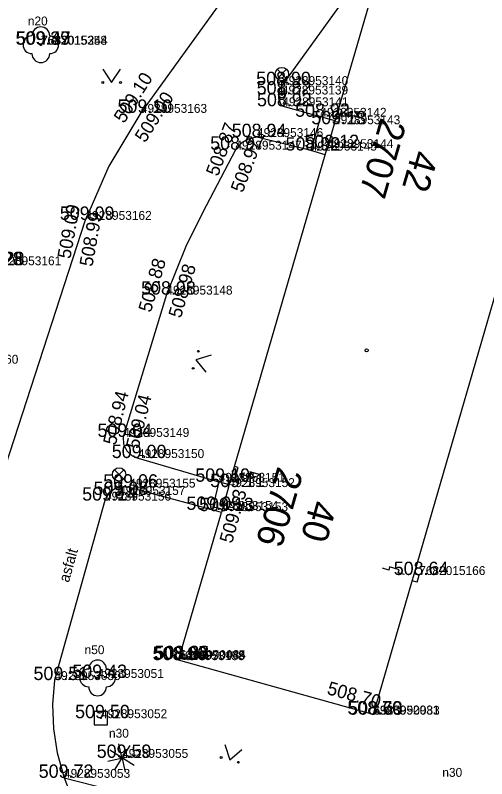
# Model space of a CAD drawing. Extents: x -669251 to -668549, y -1128351 to -1127698.
# Drawn here: x -668787.5 to -668761.03, y -1128134.75 to -1128091.87 of the extents above; entities that cross this region are included whole.
import ezdxf

# ---------------------------------------------------------------- set-up
doc = ezdxf.new("R2010")
doc.units = 0
for name, color, linetype in [('Vrstva 1', 7, 'Continuous'), ('Vrstva 10', 7, 'Continuous'), ('Vrstva 2', 7, 'Continuous'), ('Vrstva 22', 7, 'Continuous'), ('Vrstva 24', 7, 'Continuous'), ('Vrstva 26', 7, 'Continuous'), ('Vrstva 3', 7, 'Continuous'), ('Vrstva 33', 7, 'Continuous'), ('Vrstva 36', 7, 'Continuous'), ('Vrstva 40', 7, 'Continuous'), ('Vrstva 43', 7, 'Continuous'), ('Vrstva 44', 7, 'Continuous'), ('Vrstva 47', 7, 'Continuous'), ('Vrstva 5', 7, 'Continuous'), ('Vrstva 58', 7, 'Continuous'), ('Vrstva 6', 7, 'Continuous')]:
    doc.layers.add(name, color=color, linetype=linetype)

msp = doc.modelspace()

# ---------------------------------------------------------------- linework, layer by layer
at = {"layer": 'Vrstva 1'}
for p, q in [((-668786.069, -1128093.526), (-668786.069, -1128093.526)), ((-668786.04, -1128093.52), (-668786.04, -1128093.52)), ((-668772.52, -1128095.79), (-668772.52, -1128095.79)), ((-668772.53, -1128096.32), (-668772.53, -1128096.32)), ((-668772.51, -1128096.98), (-668772.51, -1128096.98)), ((-668780.45, -1128097.35), (-668780.45, -1128097.35)), ((-668770.37, -1128097.57), (-668770.37, -1128097.57)), ((-668769.6, -1128097.99), (-668769.6, -1128097.99)), ((-668773.93, -1128098.71), (-668773.93, -1128098.71)), ((-668775.14, -1128099.42), (-668775.14, -1128099.42)), ((-668770.91, -1128099.47), (-668770.91, -1128099.47)), ((-668769.99, -1128099.33), (-668769.99, -1128099.33)), ((-668783.56, -1128103.36), (-668783.56, -1128103.36)), ((-668779.02, -1128107.56), (-668779.02, -1128107.56)), ((-668781.45, -1128115.55), (-668781.45, -1128115.55)), ((-668780.61, -1128116.74), (-668780.61, -1128116.74)), ((-668776.08, -1128118.07), (-668776.08, -1128118.07)), ((-668781.1, -1128118.4), (-668781.1, -1128118.4)), ((-668775.52, -1128118.37), (-668775.52, -1128118.37)), ((-668782.47, -1128119.13), (-668782.47, -1128119.13)), ((-668781.67, -1128118.81), (-668781.67, -1128118.81)), ((-668776.45, -1128119.65), (-668776.45, -1128119.65)), ((-668775.9, -1128119.72), (-668775.9, -1128119.72)), ((-668764.82, -1128123.31), (-668764.82, -1128123.31)), ((-668778.34, -1128128.09), (-668778.34, -1128128.09)), ((-668778.295, -1128128.046), (-668778.295, -1128128.046)), ((-668778.271, -1128128.031), (-668778.271, -1128128.031)), ((-668785.3, -1128129.21), (-668785.3, -1128129.21)), ((-668782.88, -1128129.09), (-668782.88, -1128129.09)), ((-668767.4, -1128131.14), (-668767.4, -1128131.14)), ((-668767.385, -1128131.155), (-668767.385, -1128131.155)), ((-668782.69, -1128131.35), (-668782.69, -1128131.35)), ((-668781.51, -1128133.58), (-668781.51, -1128133.58)), ((-668784.77, -1128134.7), (-668784.77, -1128134.7))]:
    msp.add_line(p, q, dxfattribs=at)
at = {"layer": 'Vrstva 10'}
for p, q in [((-668768.553, -1128080.83), (-668780.45, -1128097.35)), ((-668767.52, -1128088.88), (-668772.52, -1128095.79)), ((-668770.37, -1128097.57), (-668772.51, -1128096.98)), ((-668770.37, -1128097.57), (-668770.91, -1128099.47)), ((-668769.545, -1128097.803), (-668770.37, -1128097.57)), ((-668770.91, -1128099.47), (-668773.93, -1128098.71)), ((-668770.097, -1128099.7), (-668770.91, -1128099.47)), ((-668789.953, -1128123.016), (-668783.56, -1128103.36)), ((-668779.02, -1128107.56), (-668781.45, -1128115.55)), ((-668780.61, -1128116.74), (-668776.08, -1128118.07)), ((-668776.08, -1128118.07), (-668776.45, -1128119.65)), ((-668775.483, -1128118.243), (-668776.08, -1128118.07)), ((-668776.45, -1128119.65), (-668781.1, -1128118.4)), ((-668782.47, -1128119.13), (-668785.3, -1128129.21)), ((-668775.924, -1128119.803), (-668776.45, -1128119.65)), ((-668784.765, -1128134.701), (-668756.23, -1128141.93))]:
    msp.add_line(p, q, dxfattribs=at)
for points in [[(-668772.52, -1128095.79), (-668772.695, -1128096.134), (-668772.717, -1128096.519), (-668772.582, -1128096.881), (-668772.51, -1128096.98)], [(-668780.45, -1128097.35), (-668782.25, -1128100.34), (-668783.56, -1128103.36)], [(-668773.93, -1128098.71), (-668774.416, -1128098.822), (-668774.842, -1128099.08), (-668775.14, -1128099.42)], [(-668775.14, -1128099.42), (-668776.987, -1128102.963), (-668777.918, -1128104.855), (-668779.02, -1128107.56)], [(-668781.45, -1128115.55), (-668781.425, -1128115.961), (-668781.247, -1128116.333), (-668780.942, -1128116.609), (-668780.61, -1128116.74)], [(-668781.1, -1128118.4), (-668781.512, -1128118.352), (-668781.911, -1128118.461), (-668782.24, -1128118.713), (-668782.47, -1128119.13)], [(-668785.3, -1128129.21), (-668785.412, -1128130.577), (-668785.365, -1128131.947), (-668785.158, -1128133.303), (-668784.765, -1128134.701)], [(-668784.765, -1128134.701), (-668784.281, -1128135.897), (-668783.622, -1128137.1), (-668783.36, -1128137.5)]]:
    msp.add_lwpolyline(points, dxfattribs=at)
at = {"layer": 'Vrstva 22'}
for p, q in [((-668781.518, -1128133.54), (-668781.69, -1128132.786)), ((-668781.076, -1128132.89), (-668781.49, -1128133.546)), ((-668781.544, -1128133.56), (-668782.2, -1128133.146)), ((-668782.304, -1128133.76), (-668781.55, -1128133.588)), ((-668781.53, -1128133.614), (-668781.944, -1128134.27)), ((-668781.502, -1128133.62), (-668781.33, -1128134.374)), ((-668780.82, -1128134.014), (-668781.476, -1128133.6)), ((-668781.47, -1128133.572), (-668780.716, -1128133.4))]:
    msp.add_line(p, q, dxfattribs=at)
for centre, radius in [((-668786.069, -1128093.526), 0.05), ((-668782.88, -1128129.09), 0.05), ((-668781.51, -1128133.58), 0.04)]:
    msp.add_circle(centre, radius, dxfattribs=at)
for centre, start, end in [((-668786.069, -1128093.026), 0, 180), ((-668786.569, -1128093.526), 90, 270), ((-668785.569, -1128093.526), 270, 90), ((-668786.069, -1128094.026), 180, 0), ((-668782.88, -1128128.59), 0, 180), ((-668783.38, -1128129.09), 90, 270), ((-668782.38, -1128129.09), 270, 90), ((-668782.88, -1128129.59), 180, 0)]:
    msp.add_arc(centre, 0.5, start, end, dxfattribs=at)
at = {"layer": 'Vrstva 24'}
for p, q in [((-668769.155, -1128097.182), (-668769.347, -1128097.126)), ((-668769.239, -1128097.47), (-668769.155, -1128097.182)), ((-668767.854, -1128097.458), (-668768.455, -1128097.282)), ((-668768.455, -1128097.282), (-668768.165, -1128097.627)), ((-668769.431, -1128097.414), (-668769.239, -1128097.47)), ((-668768.739, -1128097.345), (-668769.005, -1128097.382)), ((-668768.165, -1128097.627), (-668769.005, -1128097.382)), ((-668769.005, -1128097.382), (-668768.801, -1128097.556)), ((-668774.993, -1128117.273), (-668775.185, -1128117.217)), ((-668775.16, -1128117.849), (-668774.993, -1128117.273)), ((-668775.352, -1128117.793), (-668775.16, -1128117.849)), ((-668774.618, -1128117.58), (-668774.884, -1128117.617)), ((-668774.044, -1128117.861), (-668774.884, -1128117.617)), ((-668774.884, -1128117.617), (-668774.679, -1128117.791)), ((-668773.733, -1128117.691), (-668774.334, -1128117.516)), ((-668774.334, -1128117.516), (-668774.044, -1128117.861)), ((-668765.107, -1128123.228), (-668764.82, -1128123.311)), ((-668764.937, -1128123.713), (-668764.82, -1128123.311)), ((-668764.937, -1128123.713), (-668765.223, -1128123.63))]:
    msp.add_line(p, q, dxfattribs=at)
msp.add_lwpolyline([(-668765.647, -1128123.289), (-668766, -1128123.185), (-668765.949, -1128123.01), (-668766.479, -1128122.856), (-668766.531, -1128123.031), (-668766.885, -1128122.93)], dxfattribs=at)
at = {"layer": 'Vrstva 26'}
msp.add_lwpolyline([(-668783.065, -1128131.725), (-668782.315, -1128131.725), (-668782.315, -1128130.975), (-668783.065, -1128130.975)], close=True, dxfattribs=at)
msp.add_circle((-668782.69, -1128131.35), 0.02, dxfattribs=at)
at = {"layer": 'Vrstva 33'}
for p, q in [((-668772.795, -1128094.905), (-668772.265, -1128095.435)), ((-668772.795, -1128095.435), (-668772.265, -1128094.905)), ((-668772.53, -1128096.32), (-668772.53, -1128095.545)), ((-668781.935, -1128117.395), (-668781.405, -1128117.925)), ((-668781.935, -1128117.925), (-668781.405, -1128117.395)), ((-668781.67, -1128118.81), (-668781.67, -1128118.035))]:
    msp.add_line(p, q, dxfattribs=at)
for centre, radius in [((-668772.53, -1128095.17), 0.375), ((-668772.53, -1128096.32), 0.19), ((-668772.53, -1128096.32), 0.05), ((-668781.67, -1128117.66), 0.375), ((-668781.67, -1128118.81), 0.19), ((-668781.67, -1128118.81), 0.05)]:
    msp.add_circle(centre, radius, dxfattribs=at)
at = {"layer": 'Vrstva 36'}
for p, q in [((-668782.591, -1128094.897), (-668782.091, -1128095.647)), ((-668782.091, -1128095.647), (-668781.591, -1128094.897)), ((-668776.506, -1128110.961), (-668777.369, -1128111.221)), ((-668777.369, -1128111.221), (-668776.797, -1128111.918)), ((-668775.738, -1128132.836), (-668775.458, -1128133.693)), ((-668775.458, -1128133.693), (-668774.775, -1128133.105))]:
    msp.add_line(p, q, dxfattribs=at)
for centre in [(-668782.591, -1128095.647), (-668781.591, -1128095.647), (-668777.224, -1128110.743), (-668777.514, -1128111.699), (-668775.94, -1128133.559), (-668774.976, -1128133.827)]:
    msp.add_circle(centre, 0.05, dxfattribs=at)
at = {"layer": 'Vrstva 5'}
for p, q in [((-668769.545, -1128097.803), (-668767.17, -1128089.67)), ((-668756.25, -1128092.67), (-668767.4, -1128131.14)), ((-668769.6, -1128097.99), (-668769.545, -1128097.803)), ((-668770.097, -1128099.7), (-668769.99, -1128099.33)), ((-668775.483, -1128118.243), (-668770.097, -1128099.7)), ((-668775.52, -1128118.37), (-668775.483, -1128118.243)), ((-668778.34, -1128128.09), (-668775.924, -1128119.803)), ((-668767.4, -1128131.14), (-668778.34, -1128128.09))]:
    msp.add_line(p, q, dxfattribs=at)
at = {"layer": 'Vrstva 58'}
msp.add_circle((-668767.773, -1128110.693), 0.0875, dxfattribs=at)
at = {"layer": 'Vrstva 6'}
for p, q in [((-668769.6, -1128097.99), (-668769.99, -1128099.33)), ((-668775.52, -1128118.37), (-668775.924, -1128119.803))]:
    msp.add_line(p, q, dxfattribs=at)

# ---------------------------------------------------------------- texts
at = {"layer": 'Vrstva 2'}
for s, p in [('7682015358', (-668786.069, -1128093.526)), ('7682015244', (-668786.04, -1128093.52)), ('4928953140', (-668772.52, -1128095.79)), ('4928953139', (-668772.53, -1128096.32)), ('4928953141', (-668772.51, -1128096.98)), ('4928953163', (-668780.45, -1128097.35)), ('4928953142', (-668770.37, -1128097.57)), ('4928953143', (-668769.6, -1128097.99)), ('4928953146', (-668773.93, -1128098.71)), ('4928953147', (-668775.14, -1128099.42)), ('4928953145', (-668770.91, -1128099.47)), ('4928953144', (-668769.99, -1128099.33)), ('4928953162', (-668783.56, -1128103.36)), ('4928953161', (-668788.64, -1128105.91)), ('4928953148', (-668779.02, -1128107.56)), ('4928953160', (-668791.05, -1128111.44)), ('4928953149', (-668781.45, -1128115.55)), ('4928953150', (-668780.61, -1128116.74)), ('4928953155', (-668781.1, -1128118.4)), ('4928953151', (-668776.08, -1128118.07)), ('4928953152', (-668775.52, -1128118.37)), ('4928953157', (-668781.67, -1128118.81)), ('4928953156', (-668782.47, -1128119.13)), ('4928953154', (-668776.45, -1128119.65)), ('4928953153', (-668775.9, -1128119.72)), ('7682015166', (-668764.82, -1128123.31)), ('4928953158', (-668778.34, -1128128.09)), ('5496970445', (-668778.295, -1128128.046)), ('6385990084', (-668778.271, -1128128.031)), ('4928953051', (-668782.88, -1128129.09)), ('4928953050', (-668785.3, -1128129.21)), ('4928952931', (-668767.4, -1128131.14)), ('6385990083', (-668767.385, -1128131.155)), ('4928953052', (-668782.69, -1128131.35)), ('4928953055', (-668781.51, -1128133.58)), ('4928953053', (-668784.77, -1128134.7))]:
    msp.add_text(s, height=0.5, dxfattribs=at).set_placement(p)
at = {"layer": 'Vrstva 3'}
for s, p in [('509.39 ', (-668787.489, -1128093.526)), ('509.47 ', (-668787.457, -1128093.52)), ('508.90 ', (-668773.973, -1128095.79)), ('508.82 ', (-668773.945, -1128096.32)), ('508.92 ', (-668773.927, -1128096.98)), ('509.10 ', (-668781.761, -1128097.35)), ('508.92 ', (-668771.787, -1128097.57)), ('509.13 ', (-668770.876, -1128097.99)), ('508.94 ', (-668775.347, -1128098.71)), ('509.12 ', (-668771.266, -1128099.33)), ('508.97 ', (-668776.557, -1128099.42)), ('508.92 ', (-668772.327, -1128099.47)), ('509.09 ', (-668785.002, -1128103.36)), ('509.28 ', (-668790.16, -1128105.91)), ('509.28 ', (-668790.057, -1128105.91)), ('508.98 ', (-668780.437, -1128107.56)), ('509.04 ', (-668782.888, -1128115.55)), ('509.00 ', (-668782.084, -1128116.74)), ('509.10 ', (-668777.391, -1128118.07)), ('509.06 ', (-668782.562, -1128118.4)), ('509.11 ', (-668776.559, -1128118.37)), ('509.08 ', (-668783.108, -1128118.81)), ('509.14 ', (-668783.746, -1128119.13)), ('509.09 ', (-668777.892, -1128119.65)), ('509.13 ', (-668777.176, -1128119.72)), ('508.64 ', (-668766.249, -1128123.31)), ('508.90 ', (-668779.793, -1128128.09)), ('508.87 ', (-668779.71, -1128128.046)), ('508.88 ', (-668779.686, -1128128.031)), ('509.51 ', (-668786.48, -1128129.21)), ('509.43 ', (-668784.297, -1128129.09)), ('509.50 ', (-668784.143, -1128131.35)), ('508.70 ', (-668768.851, -1128131.14)), ('508.63 ', (-668768.814, -1128131.155)), ('509.59 ', (-668782.93, -1128133.58)), ('509.72 ', (-668786.187, -1128134.7))]:
    msp.add_text(s, height=0.75, dxfattribs=at).set_placement(p)
for s, rotation, p in [('509.10 ', 57.6453, (-668781.392, -1128097.981)), ('509.00 ', 57.6453, (-668780.211, -1128099.069)), ('508.87 ', 69.1908, (-668776.124, -1128100.959)), ('508.97 ', 69.1908, (-668774.734, -1128101.88)), ('509.09 ', 79.7104, (-668784.412, -1128105.587)), ('508.99 ', 79.7104, (-668783.173, -1128106.021)), ('508.88 ', 73.7271, (-668779.891, -1128108.601)), ('508.98 ', 73.7271, (-668778.204, -1128108.919)), ('508.94 ', 75.9918, (-668781.865, -1128116.058)), ('509.04 ', 75.9918, (-668780.58, -1128116.258)), ('509.13 ', 74.2791, (-668775.33, -1128121.57)), ('508.70 ', 344.4219, (-668770.042, -1128129.989))]:
    msp.add_text(s, height=0.75, rotation=rotation, dxfattribs=at).set_placement(p)
at = {"layer": 'Vrstva 40'}
msp.add_text('asfalt', height=0.6, rotation=74.3177, dxfattribs=at).set_placement((-668784.497, -1128123.761))
at = {"layer": 'Vrstva 43'}
for s, p in [('2707', (-668766.967, -1128097.565)), ('2706', (-668772.757, -1128117.158))]:
    msp.add_text(s, height=1.5, rotation=253.8035, dxfattribs=at).set_placement(p)
at = {"layer": 'Vrstva 44'}
for s, rotation, p in [('42', 253.7726, (-668765.168, -1128099.372)), ('40', 254.2791, (-668770.879, -1128119.034))]:
    msp.add_text(s, height=1.5, rotation=rotation, dxfattribs=at).set_placement(p)
at = {"layer": 'Vrstva 47'}
for s, height, p in [('n20', 0.499, (-668786.798, -1128092.44)), ('n50', 0.499, (-668783.609, -1128127.754)), ('n30', 0.5, (-668782.24, -1128132.444)), ('n30', 0.5, (-668763.52, -1128134.644))]:
    msp.add_text(s, height=height, dxfattribs=at).set_placement(p)

doc.saveas('drawing.dxf')
